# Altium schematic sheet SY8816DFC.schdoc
size 127 x 101 mm
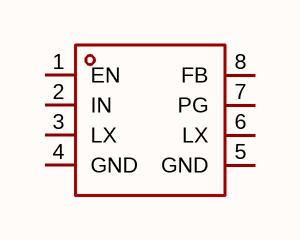
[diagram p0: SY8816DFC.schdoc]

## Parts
U?  sy8816dfc  [DFN-8_L2.0-W2.0_SY8816DFC]  (value not drawn)

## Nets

Not connected (* = marked no-connect by the designer): U? 1(EN) 2(IN) 3(LX) 4(GND) 5(GND) 6(LX) 7(PG) 8(FB)

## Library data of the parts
U? = sy8816dfc: 功能类型:降压型;工作电压:2.75V~6V;输出电压:-;输出电流:6A;输出类型:可调;; Manufacturer: Silergy(矽力杰); AddInBom: yes; ModelId: 84abb5f2fbe24c19b87ac527fa317a32; ModelTransform: 79.527,79.527,0,0,0,0,-9.842,0,0; Function: 降压型; Output Current: 6A; Frequency - Switching: 1.2MHz; Synchronous Rectifier: 是; Number of Outputs: 1; Topology: 降压式; Quiescent Current: 60uA; Switch tube (built-in/external): 内置; Output Type: 可调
